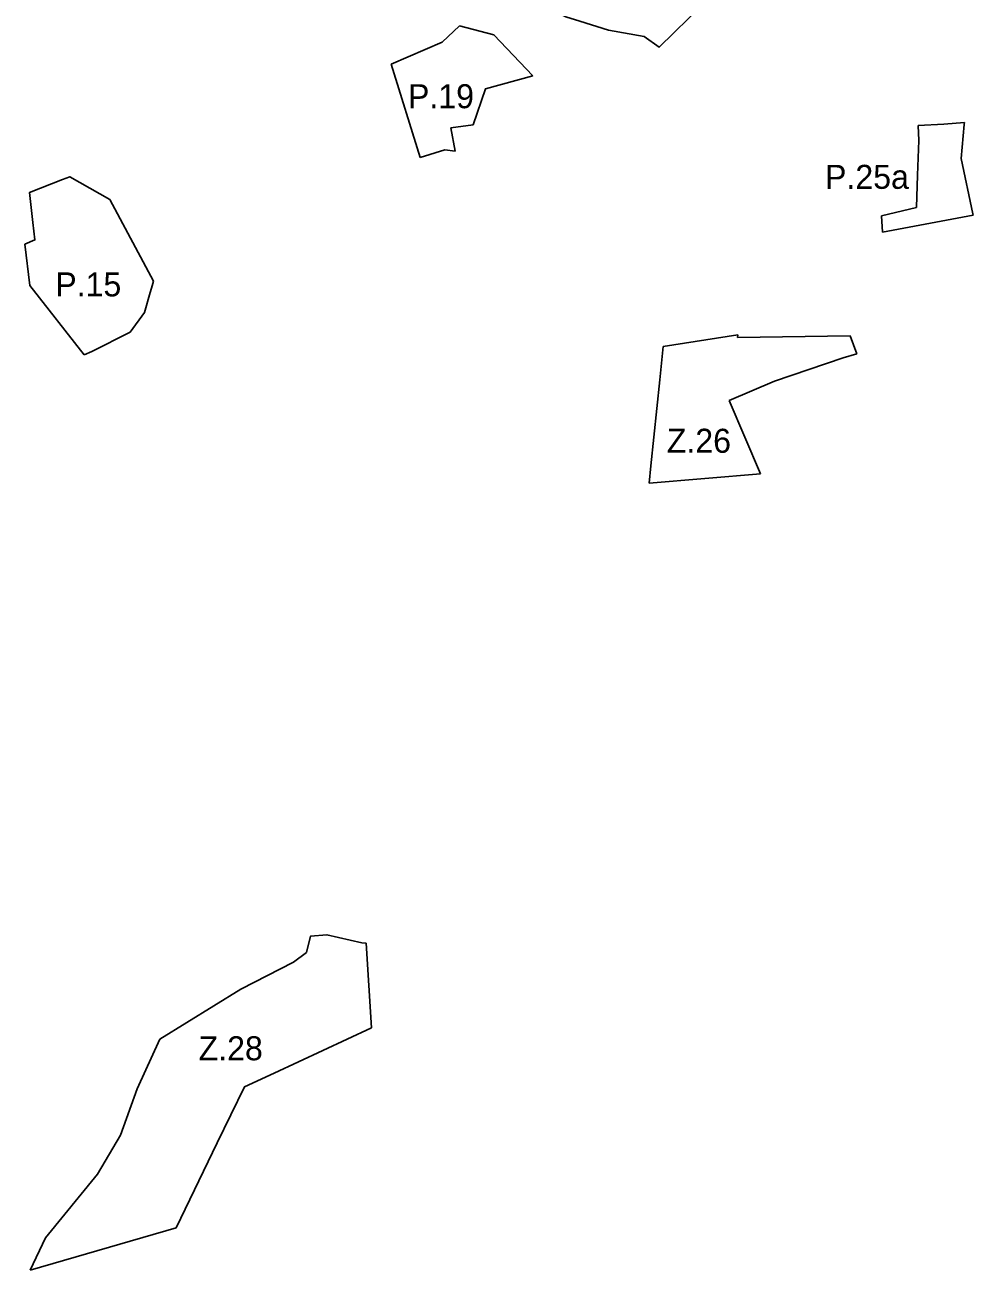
# Model space of a CAD drawing. Extents: x -438701 to -435614, y -1126017 to -1121766.
# Drawn here: x -438257 to -437862, y -1124623 to -1124104 of the extents above; entities that cross this region are included whole.
import ezdxf

# ---------------------------------------------------------------- set-up
doc = ezdxf.new("R2010")
doc.units = 0
for name, color, linetype in [('NAVRH', 7, 'Continuous'), ('STAV', 7, 'Continuous'), ('Vrstva 3', 7, 'Continuous'), ('Vrstva 6', 7, 'Continuous'), ('Vrstva 7', 7, 'Continuous'), ('Vrstva 9', 7, 'Continuous')]:
    doc.layers.add(name, color=color, linetype=linetype)

msp = doc.modelspace()

# ---------------------------------------------------------------- linework, layer by layer
at = {"layer": 'NAVRH'}
for p, q in [((-437960.31, -1124233.42), (-437991.49, -1124238.36)), ((-437960.47, -1124234.63), (-437960.31, -1124233.42)), ((-437913.63, -1124233.96), (-437960.47, -1124234.63)), ((-437910.79, -1124241.36), (-437913.63, -1124233.96)), ((-437991.49, -1124238.36), (-437992.92, -1124252.28)), ((-437945.08, -1124252.79), (-437916.45, -1124243.12)), ((-437916.45, -1124243.12), (-437910.79, -1124241.36)), ((-437992.92, -1124252.28), (-437996.6, -1124288.08)), ((-437963.96, -1124260.77), (-437945.08, -1124252.79)), ((-437950.96, -1124291.38), (-437963.96, -1124260.77)), ((-437996.6, -1124288.08), (-437997.33, -1124295.28)), ((-437997.33, -1124295.28), (-437950.96, -1124291.38)), ((-438115.2, -1124486.87), (-438116.97, -1124486.82)), ((-438112.99, -1124522.16), (-438115.2, -1124486.87)), ((-438153.62, -1124541.08), (-438112.99, -1124522.16)), ((-438201.18, -1124526.86), (-438210.62, -1124547.67)), ((-438194.46, -1124605.47), (-438177.26, -1124570.11)), ((-438227.14, -1124583.16), (-438248.86, -1124609.63)), ((-438255.22, -1124623.13), (-438194.46, -1124605.47)), ((-438248.86, -1124609.63), (-438255.22, -1124623.13))]:
    msp.add_line(p, q, dxfattribs=at)
for points in [[(-438116.97, -1124486.82), (-438131.6, -1124483.4), (-438138.36, -1124483.99), (-438140.06, -1124490.77), (-438145.57, -1124494.8), (-438167.42, -1124506.04), (-438201.18, -1124526.86)], [(-438177.26, -1124570.11), (-438165.93, -1124546.81), (-438153.62, -1124541.08)], [(-438210.62, -1124547.67), (-438217.61, -1124566.88), (-438227.14, -1124583.16)]]:
    msp.add_lwpolyline(points, dxfattribs=at)
at = {"layer": 'Vrstva 3'}
for p, q in [((-438076.4, -1124104.72), (-438083.57, -1124111.52)), ((-438062.04, -1124108.49), (-438076.4, -1124104.72)), ((-438045.82, -1124125.58), (-438062.04, -1124108.49)), ((-438083.57, -1124111.52), (-438104.84, -1124120.64)), ((-438104.84, -1124120.64), (-438092.69, -1124159.53)), ((-438080.02, -1124147.3), (-438070.71, -1124146.05)), ((-437874.57, -1124145.67), (-437885.28, -1124146.23)), ((-437885.28, -1124146.23), (-437884.95, -1124152.49)), ((-437865.97, -1124145.07), (-437874.57, -1124145.67)), ((-438078.15, -1124156.98), (-438080.02, -1124147.3)), ((-438092.69, -1124159.53), (-438082.52, -1124156.36)), ((-438082.52, -1124156.36), (-438078.15, -1124156.98)), ((-437884.95, -1124152.49), (-437885.46, -1124166.92)), ((-437862.45, -1124183.13), (-437867.28, -1124159.99)), ((-437885.46, -1124166.92), (-437885.94, -1124180.45)), ((-438203.88, -1124211.06), (-438221.99, -1124177.08)), ((-437885.94, -1124180.45), (-437900.49, -1124183.93)), ((-437862.35, -1124183.6), (-437862.45, -1124183.13)), ((-437900.49, -1124183.93), (-437900.15, -1124190.67)), ((-437900.15, -1124190.67), (-437862.35, -1124183.6)), ((-438257.42, -1124195.72), (-438255.35, -1124212.94)), ((-438255.35, -1124212.94), (-438232.66, -1124241.79)), ((-438205.19, -1124215.8), (-438204.71, -1124214.06)), ((-438204.71, -1124214.06), (-438203.88, -1124211.06)), ((-438207.53, -1124224.23), (-438205.19, -1124215.8)), ((-438213.5, -1124232.33), (-438207.53, -1124224.23)), ((-438229.6, -1124240.42), (-438213.5, -1124232.33)), ((-438232.66, -1124241.79), (-438229.6, -1124240.42))]:
    msp.add_line(p, q, dxfattribs=at)
for points in [[(-438036.43, -1124098.7), (-438032.06, -1124100.94), (-438026.23, -1124102.79), (-438014.26, -1124106.6), (-437999.46, -1124109.17), (-437993.22, -1124113.66), (-437974.68, -1124095.62), (-437961.27, -1124082.58)], [(-438070.71, -1124146.05), (-438065.51, -1124130.95), (-438045.82, -1124125.58)], [(-437867.28, -1124159.99), (-437866.04, -1124145.89), (-437865.97, -1124145.07)], [(-438221.99, -1124177.08), (-438238.76, -1124167.62), (-438241.8, -1124168.81)], [(-438241.8, -1124168.81), (-438255.49, -1124174.16), (-438254.08, -1124186.73), (-438253.27, -1124193.94), (-438257.42, -1124195.72)]]:
    msp.add_lwpolyline(points, dxfattribs=at)
at = {"layer": 'Vrstva 6'}
for p, q in [((-437960.31, -1124233.42), (-437991.49, -1124238.36)), ((-437960.47, -1124234.63), (-437960.31, -1124233.42)), ((-437913.63, -1124233.96), (-437960.47, -1124234.63)), ((-437910.79, -1124241.36), (-437913.63, -1124233.96)), ((-437991.49, -1124238.36), (-437992.92, -1124252.28)), ((-437945.08, -1124252.79), (-437916.45, -1124243.12)), ((-437916.45, -1124243.12), (-437910.79, -1124241.36)), ((-437992.92, -1124252.28), (-437996.6, -1124288.08)), ((-437963.96, -1124260.77), (-437945.08, -1124252.79)), ((-437950.96, -1124291.38), (-437963.96, -1124260.77)), ((-437996.6, -1124288.08), (-437997.33, -1124295.28)), ((-437997.33, -1124295.28), (-437950.96, -1124291.38)), ((-438115.2, -1124486.87), (-438116.97, -1124486.82)), ((-438112.99, -1124522.16), (-438115.2, -1124486.87)), ((-438153.62, -1124541.08), (-438112.99, -1124522.16)), ((-438201.18, -1124526.86), (-438210.62, -1124547.67)), ((-438194.46, -1124605.47), (-438177.26, -1124570.11)), ((-438227.14, -1124583.16), (-438248.86, -1124609.63)), ((-438255.22, -1124623.13), (-438194.46, -1124605.47)), ((-438248.86, -1124609.63), (-438255.22, -1124623.13))]:
    msp.add_line(p, q, dxfattribs=at)
for points in [[(-438116.97, -1124486.82), (-438131.6, -1124483.4), (-438138.36, -1124483.99), (-438140.06, -1124490.77), (-438145.57, -1124494.8), (-438167.42, -1124506.04), (-438201.18, -1124526.86)], [(-438177.26, -1124570.11), (-438165.93, -1124546.81), (-438153.62, -1124541.08)], [(-438210.62, -1124547.67), (-438217.61, -1124566.88), (-438227.14, -1124583.16)]]:
    msp.add_lwpolyline(points, dxfattribs=at)
at = {"layer": 'Vrstva 7'}
for p, q in [((-438076.4, -1124104.72), (-438083.57, -1124111.52)), ((-438062.04, -1124108.49), (-438076.4, -1124104.72)), ((-438045.82, -1124125.58), (-438062.04, -1124108.49)), ((-438083.57, -1124111.52), (-438104.84, -1124120.64)), ((-438104.84, -1124120.64), (-438092.69, -1124159.53)), ((-438080.02, -1124147.3), (-438070.71, -1124146.05)), ((-437874.57, -1124145.67), (-437885.28, -1124146.23)), ((-437885.28, -1124146.23), (-437884.95, -1124152.49)), ((-437865.97, -1124145.07), (-437874.57, -1124145.67)), ((-438078.15, -1124156.98), (-438080.02, -1124147.3)), ((-438092.69, -1124159.53), (-438082.52, -1124156.36)), ((-438082.52, -1124156.36), (-438078.15, -1124156.98)), ((-437884.95, -1124152.49), (-437885.46, -1124166.92)), ((-437862.45, -1124183.13), (-437867.28, -1124159.99)), ((-437885.46, -1124166.92), (-437885.94, -1124180.45)), ((-438203.88, -1124211.06), (-438221.99, -1124177.08)), ((-437885.94, -1124180.45), (-437900.49, -1124183.93)), ((-437862.35, -1124183.6), (-437862.45, -1124183.13)), ((-437900.49, -1124183.93), (-437900.15, -1124190.67)), ((-437900.15, -1124190.67), (-437862.35, -1124183.6)), ((-438257.42, -1124195.72), (-438255.35, -1124212.94)), ((-438255.35, -1124212.94), (-438232.66, -1124241.79)), ((-438205.19, -1124215.8), (-438204.71, -1124214.06)), ((-438204.71, -1124214.06), (-438203.88, -1124211.06)), ((-438207.53, -1124224.23), (-438205.19, -1124215.8)), ((-438213.5, -1124232.33), (-438207.53, -1124224.23)), ((-438229.6, -1124240.42), (-438213.5, -1124232.33)), ((-438232.66, -1124241.79), (-438229.6, -1124240.42))]:
    msp.add_line(p, q, dxfattribs=at)
for points in [[(-438036.43, -1124098.7), (-438032.06, -1124100.94), (-438026.23, -1124102.79), (-438014.26, -1124106.6), (-437999.46, -1124109.17), (-437993.22, -1124113.66), (-437974.68, -1124095.62), (-437961.27, -1124082.58)], [(-438070.71, -1124146.05), (-438065.51, -1124130.95), (-438045.82, -1124125.58)], [(-437867.28, -1124159.99), (-437866.04, -1124145.89), (-437865.97, -1124145.07)], [(-438221.99, -1124177.08), (-438238.76, -1124167.62), (-438241.8, -1124168.81)], [(-438241.8, -1124168.81), (-438255.49, -1124174.16), (-438254.08, -1124186.73), (-438253.27, -1124193.94), (-438257.42, -1124195.72)]]:
    msp.add_lwpolyline(points, dxfattribs=at)

# ---------------------------------------------------------------- texts
at = {"layer": 'STAV'}
for s, p in [('P.19', (-438097.81, -1124139.06)), ('P.25a', (-437924.04, -1124172.65)), ('P.15', (-438244.77, -1124217.46))]:
    msp.add_text(s, height=10, dxfattribs=at).set_placement(p)
at = {"layer": 'Vrstva 9'}
for s, p in [('Z.26', (-437989.98, -1124282.61)), ('Z.28', (-438185.05, -1124535.71))]:
    msp.add_text(s, height=10, dxfattribs=at).set_placement(p)

doc.saveas('drawing.dxf')
